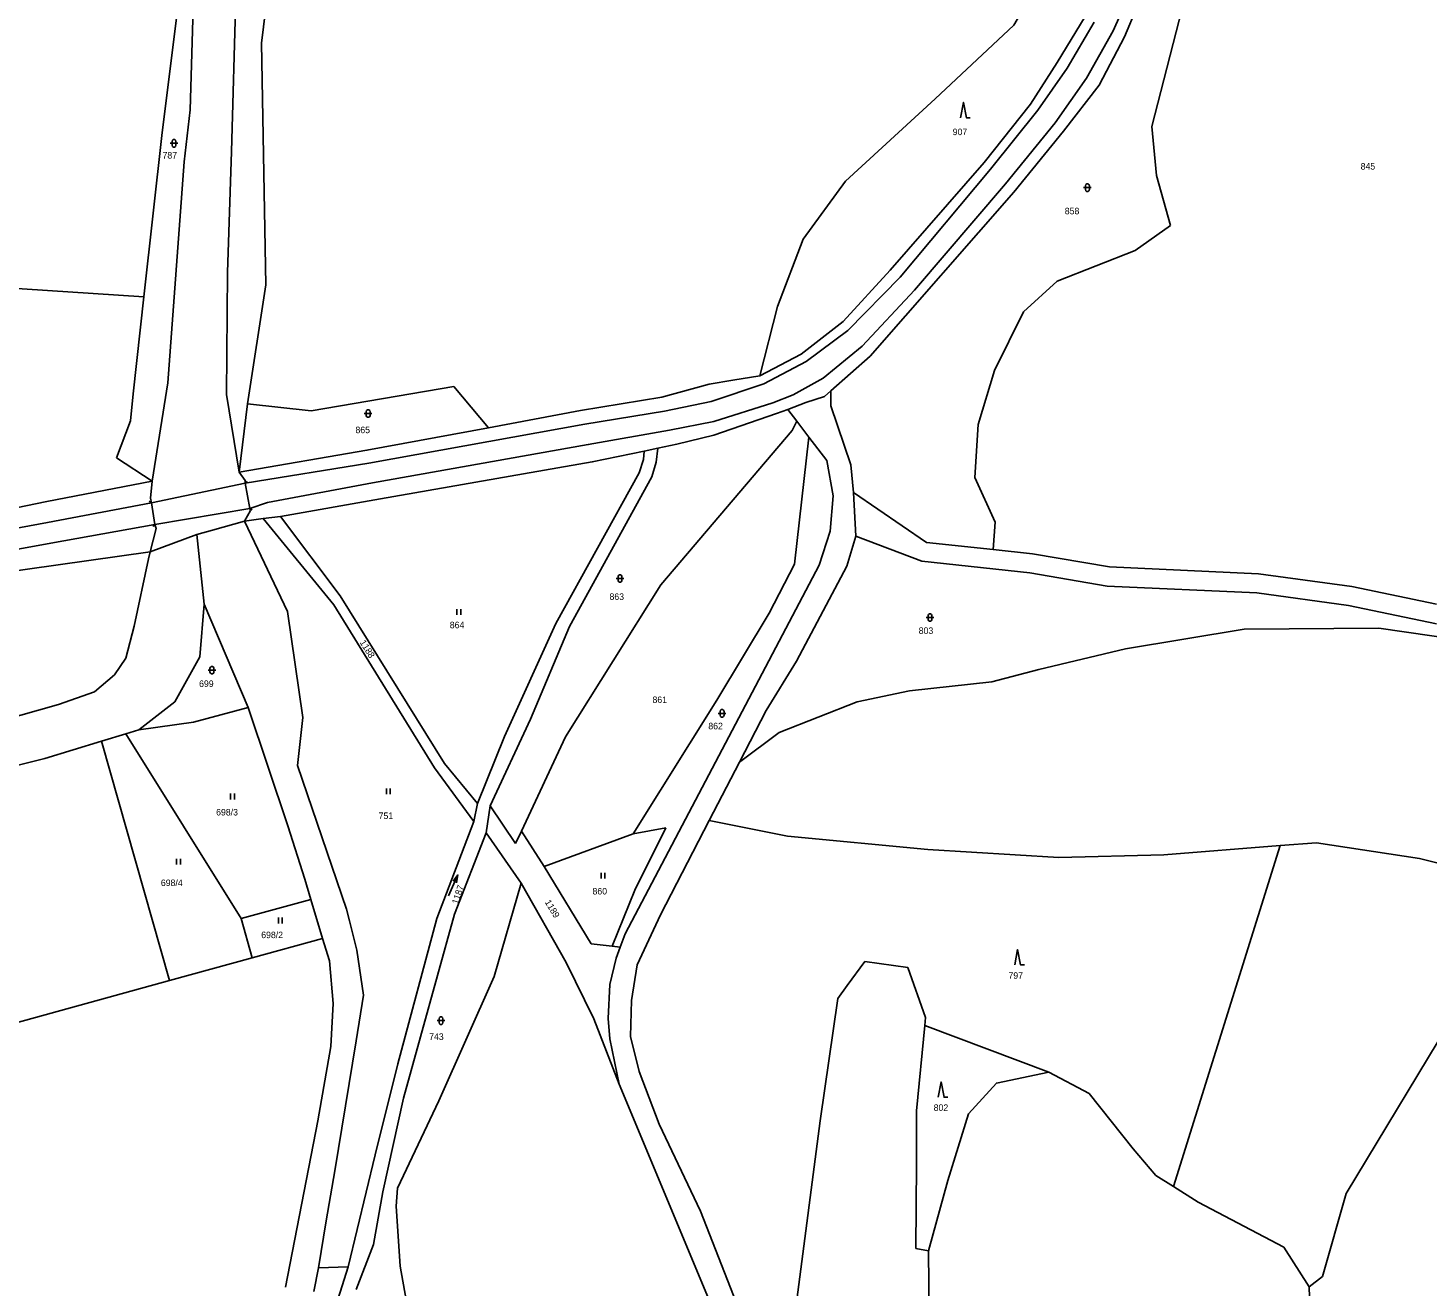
# Model space of a CAD drawing. Extents: x -812394 to -807601, y -1013097 to -1009266.
# Drawn here: x -809418.3 to -809053.2, y -1010907 to -1010578.9 of the extents above; entities that cross this region are included whole.
import ezdxf

# ---------------------------------------------------------------- set-up
doc = ezdxf.new("R2010")
doc.units = 0
for name, color, linetype in [('Default', 7, 'Continuous'), ('KN_HRANICE', 7, 'Continuous'), ('KN_KULTURY', 7, 'Continuous'), ('KN_PARCELY', 7, 'Continuous'), ('KN_SLUCKY', 7, 'Continuous')]:
    doc.layers.add(name, color=color, linetype=linetype)

# ---------------------------------------------------------------- blocks, each defined once
blk = doc.blocks.new('4201')
at = {"layer": 'Default'}
blk.add_line((0, 0), (-0.5, -0.5), dxfattribs=at)
blk = doc.blocks.new('306')
at = {"layer": 'Default'}
for p, q in [((-0.5, 1.5), (-0.5, 0)), ((0.5, 0), (0.5, 1.5))]:
    blk.add_line(p, q, dxfattribs=at)
blk = doc.blocks.new('308')
at = {"layer": 'Default'}
blk.add_lwpolyline([(-0.75, 0), (0, 4), (0.75, 0), (1.75, 0)], dxfattribs=at)
blk = doc.blocks.new('316')
at = {"layer": 'Default'}
for points in [[(-1, 1), (0.27, 1), (1, 1)], [(-0.5, 1.5), (-0.4, 1.79), (-0.15, 1.97), (0.16, 1.97), (0.41, 1.79), (0.51, 1.5), (0.51, 0.5), (0.41, 0.21), (0.16, 0.03), (-0.15, 0.03), (-0.4, 0.21), (-0.5, 0.5), (-0.5, 1.5)]]:
    blk.add_lwpolyline(points, dxfattribs=at)
blk = doc.blocks.new('802')
at = {"layer": 'Default'}
blk.add_line((-3, 0), (3, 0), dxfattribs=at)
blk.add_lwpolyline([(1, 0.5), (3, 0), (1, -0.5)], dxfattribs=at)

msp = doc.modelspace()

# ---------------------------------------------------------------- linework, layer by layer
at = {"layer": 'KN_HRANICE'}
for p, q in [((-809111.83, -1010552.24), (-809125.24, -1010604.55)), ((-809377.13, -1010557.12), (-809383.35, -1010606.11)), ((-809363.71, -1010556.15), (-809365.25, -1010611.02)), ((-809357.41, -1010582.83), (-809354.36, -1010558.01)), ((-809375.97, -1010600.22), (-809375.07, -1010568.14)), ((-809132.35, -1010581.13), (-809129.18, -1010573.51)), ((-809142.65, -1010575.85), (-809149.94, -1010587.88)), ((-809139.03, -1010593.73), (-809132.35, -1010581.13)), ((-809356.31, -1010645.84), (-809357.41, -1010582.83)), ((-809149.94, -1010587.88), (-809156.85, -1010598.68)), ((-809148.29, -1010605.74), (-809139.03, -1010593.73)), ((-809156.85, -1010598.68), (-809169, -1010613.92)), ((-809377.56, -1010613.76), (-809375.97, -1010600.22)), ((-809383.35, -1010606.11), (-809388.09, -1010648.93)), ((-809161.26, -1010621.62), (-809148.29, -1010605.74)), ((-809125.24, -1010604.55), (-809124.05, -1010617.34)), ((-809381.8, -1010671.36), (-809377.56, -1010613.76)), ((-809365.25, -1010611.02), (-809366.29, -1010642.62)), ((-809169, -1010613.92), (-809193.46, -1010642)), ((-809124.05, -1010617.34), (-809120.37, -1010630.38)), ((-809198.7, -1010664.41), (-809161.26, -1010621.62)), ((-809120.37, -1010630.38), (-809129.56, -1010636.86)), ((-809129.56, -1010636.86), (-809149.97, -1010644.82)), ((-809366.29, -1010642.62), (-809366.56, -1010674.35)), ((-809193.46, -1010642), (-809205.76, -1010655.37)), ((-809388.09, -1010648.93), (-809445.19, -1010645.2)), ((-809361.06, -1010676.78), (-809356.31, -1010645.84)), ((-809149.97, -1010644.82), (-809158.75, -1010652.82)), ((-809390.89, -1010674.22), (-809388.09, -1010648.93)), ((-809158.75, -1010652.82), (-809166.27, -1010668.11)), ((-809205.76, -1010655.37), (-809216.72, -1010663.86)), ((-809216.72, -1010663.86), (-809227.49, -1010669.52)), ((-809208.98, -1010673.47), (-809198.7, -1010664.41)), ((-809166.27, -1010668.11), (-809170.54, -1010682.2)), ((-809385.89, -1010696.99), (-809381.8, -1010671.36)), ((-809307.29, -1010672.33), (-809344.46, -1010678.63)), ((-809298.22, -1010683.04), (-809307.29, -1010672.33)), ((-809240.7, -1010671.73), (-809253.03, -1010675.1)), ((-809234.5, -1010670.64), (-809240.7, -1010671.73)), ((-809227.49, -1010669.52), (-809234.5, -1010670.64)), ((-809391.53, -1010681.27), (-809390.89, -1010674.22)), ((-809366.56, -1010674.35), (-809363.24, -1010694.6)), ((-809253.03, -1010675.1), (-809274.21, -1010678.59)), ((-809210.6, -1010674.9), (-809215.44, -1010676.51)), ((-809210.6, -1010674.9), (-809208.98, -1010673.47)), ((-809208.98, -1010677.34), (-809208.98, -1010673.47)), ((-809363.24, -1010694.6), (-809361.06, -1010676.78)), ((-809344.46, -1010678.63), (-809361.06, -1010676.78)), ((-809274.21, -1010678.59), (-809298.22, -1010683.04)), ((-809239.47, -1010685.01), (-809223.12, -1010679.37)), ((-809223.12, -1010679.37), (-809220.13, -1010678.26)), ((-809220.13, -1010678.26), (-809215.44, -1010676.51)), ((-809220.13, -1010678.26), (-809217.82, -1010681.31)), ((-809203.72, -1010692.71), (-809208.98, -1010677.34)), ((-809395.22, -1010690.85), (-809391.53, -1010681.27)), ((-809217.82, -1010681.31), (-809219.05, -1010683.79)), ((-809217.82, -1010681.31), (-809214.65, -1010685.5)), ((-809170.54, -1010682.2), (-809171.37, -1010695.98)), ((-809219.05, -1010683.79), (-809253.31, -1010723.95)), ((-809249.11, -1010687.36), (-809239.47, -1010685.01)), ((-809218.43, -1010718.59), (-809214.65, -1010685.5)), ((-809214.65, -1010685.5), (-809210.02, -1010691.61)), ((-809254.05, -1010688.39), (-809257.64, -1010689.14)), ((-809254.05, -1010688.39), (-809254.52, -1010692.03)), ((-809249.11, -1010687.36), (-809254.05, -1010688.39)), ((-809385.89, -1010696.99), (-809395.22, -1010690.85)), ((-809254.52, -1010692.03), (-809255.59, -1010695.88)), ((-809210.02, -1010691.61), (-809208.36, -1010700.77)), ((-809203.06, -1010699.92), (-809203.72, -1010692.71)), ((-809413.39, -1010702.26), (-809385.89, -1010696.99)), ((-809360.44, -1010704.12), (-809361.63, -1010697.51)), ((-809255.59, -1010695.88), (-809277.13, -1010734.81)), ((-809171.37, -1010695.98), (-809166.1, -1010707.64)), ((-809208.36, -1010700.77), (-809209.11, -1010710.03)), ((-809183.97, -1010712.92), (-809203.06, -1010699.92)), ((-809203.06, -1010699.92), (-809202.45, -1010711.33)), ((-809413.39, -1010702.26), (-809437.86, -1010707.26)), ((-809385.19, -1010708.29), (-809386.06, -1010702.58)), ((-809370.19, -1010709.75), (-809361.8, -1010707.43)), ((-809356.99, -1010706.69), (-809361.8, -1010707.43)), ((-809361.8, -1010707.43), (-809350.65, -1010730.95)), ((-809352.49, -1010706.15), (-809356.99, -1010706.69)), ((-809356.99, -1010706.69), (-809338.51, -1010729.21)), ((-809336.86, -1010726.87), (-809352.49, -1010706.15)), ((-809166.1, -1010707.64), (-809166.67, -1010714.78)), ((-809374.26, -1010710.88), (-809386.46, -1010715.35)), ((-809370.19, -1010709.75), (-809374.26, -1010710.88)), ((-809372.39, -1010729.01), (-809374.26, -1010710.88)), ((-809209.11, -1010710.03), (-809212.01, -1010718.89)), ((-809204.77, -1010719.08), (-809202.45, -1010711.33)), ((-809202.45, -1010711.33), (-809185.19, -1010717.8)), ((-809434.83, -1010722.26), (-809386.46, -1010715.35)), ((-809386.46, -1010715.35), (-809386.86, -1010717.18)), ((-809166.67, -1010714.78), (-809183.97, -1010712.92)), ((-809156.41, -1010715.89), (-809166.67, -1010714.78)), ((-809136.31, -1010719.31), (-809156.41, -1010715.89)), ((-809212.01, -1010718.89), (-809262.62, -1010814.93)), ((-809225, -1010731.39), (-809218.43, -1010718.59)), ((-809217.89, -1010743.91), (-809204.77, -1010719.08)), ((-809185.19, -1010717.8), (-809157.07, -1010720.85)), ((-809097.41, -1010721.08), (-809136.31, -1010719.31)), ((-809157.07, -1010720.85), (-809136.87, -1010724.29)), ((-809073.09, -1010724.43), (-809097.41, -1010721.08)), ((-809309.65, -1010770.56), (-809336.86, -1010726.87)), ((-809253.31, -1010723.95), (-809278.14, -1010763.62)), ((-809136.87, -1010724.29), (-809097.85, -1010726.06)), ((-809097.85, -1010726.06), (-809073.97, -1010729.35)), ((-809051.04, -1010729.02), (-809073.09, -1010724.43)), ((-809372.39, -1010729.01), (-809360.9, -1010755.91)), ((-809350.65, -1010730.95), (-809346.62, -1010758.53)), ((-809338.51, -1010729.21), (-809312.31, -1010771.66)), ((-809073.97, -1010729.35), (-809051.02, -1010734.13)), ((-809294.04, -1010763.48), (-809280.64, -1010734.02)), ((-809238.67, -1010754.07), (-809225, -1010731.39)), ((-809277.13, -1010734.81), (-809287.3, -1010759.01)), ((-809132.16, -1010740.65), (-809101.15, -1010735.55)), ((-809101.15, -1010735.55), (-809066.09, -1010735.31)), ((-809066.09, -1010735.31), (-809035.42, -1010739.75)), ((-809154.74, -1010746.08), (-809132.16, -1010740.65)), ((-809225.81, -1010756.71), (-809217.89, -1010743.91)), ((-809166.94, -1010749.26), (-809154.74, -1010746.08)), ((-809202.08, -1010754.49), (-809188.43, -1010751.6)), ((-809188.43, -1010751.6), (-809166.94, -1010749.26)), ((-809350.5, -1010786.79), (-809360.9, -1010755.91)), ((-809260.51, -1010788.84), (-809238.67, -1010754.07)), ((-809222.4, -1010762.48), (-809202.08, -1010754.49)), ((-809346.62, -1010758.53), (-809348.01, -1010771.1)), ((-809287.3, -1010759.01), (-809297.76, -1010781.54)), ((-809232.78, -1010770.16), (-809225.81, -1010756.71)), ((-809399.13, -1010764.75), (-809392.8, -1010762.82)), ((-809392.8, -1010762.82), (-809389.38, -1010761.78)), ((-809392.8, -1010762.82), (-809362.69, -1010810.95)), ((-809301.09, -1010780.94), (-809294.04, -1010763.48)), ((-809278.14, -1010763.62), (-809289.64, -1010788.2)), ((-809232.78, -1010770.16), (-809222.4, -1010762.48)), ((-809413.92, -1010769.26), (-809399.13, -1010764.75)), ((-809399.13, -1010764.75), (-809381.38, -1010827.1)), ((-809450.75, -1010778.5), (-809413.92, -1010769.26)), ((-809301.09, -1010780.94), (-809309.65, -1010770.56)), ((-809240.68, -1010785.42), (-809232.78, -1010770.16)), ((-809312.31, -1010771.66), (-809302.07, -1010785.66)), ((-809302.07, -1010785.66), (-809301.09, -1010780.94)), ((-809297.76, -1010781.54), (-809298.85, -1010788.58)), ((-809291.14, -1010791.4), (-809297.76, -1010781.54)), ((-809311.7, -1010810.97), (-809302.07, -1010785.66)), ((-809253.38, -1010809.96), (-809240.68, -1010785.42)), ((-809220.26, -1010789.46), (-809240.68, -1010785.42)), ((-809346.14, -1010800.65), (-809350.5, -1010786.79)), ((-809298.85, -1010788.58), (-809307.08, -1010809.79)), ((-809298.85, -1010788.58), (-809289.73, -1010801.7)), ((-809289.64, -1010788.2), (-809291.14, -1010791.4)), ((-809283.71, -1010797.35), (-809289.64, -1010788.2)), ((-809283.71, -1010797.35), (-809260.51, -1010788.84)), ((-809260.51, -1010788.84), (-809252.02, -1010787.31)), ((-809260.08, -1010803.57), (-809252.02, -1010787.31)), ((-809183.63, -1010792.94), (-809220.26, -1010789.46)), ((-809149.52, -1010795.02), (-809183.63, -1010792.94)), ((-809091.8, -1010791.95), (-809122.15, -1010794.33)), ((-809119.63, -1010880.82), (-809091.8, -1010791.95)), ((-809082.28, -1010791.2), (-809091.8, -1010791.95)), ((-809055.45, -1010795.34), (-809082.28, -1010791.2)), ((-809122.15, -1010794.33), (-809149.52, -1010795.02)), ((-809029.02, -1010801.9), (-809055.45, -1010795.34)), ((-809271.44, -1010817.56), (-809283.71, -1010797.35)), ((-809344.54, -1010805.97), (-809346.14, -1010800.65)), ((-809289.73, -1010801.7), (-809296.75, -1010826.06)), ((-809289.73, -1010801.7), (-809277.95, -1010822.39)), ((-809265.96, -1010818.15), (-809260.08, -1010803.57)), ((-809362.69, -1010810.95), (-809344.54, -1010805.97)), ((-809341.48, -1010816.14), (-809344.54, -1010805.97)), ((-809359.87, -1010821.19), (-809362.69, -1010810.95)), ((-809321.83, -1010848.82), (-809311.7, -1010810.97)), ((-809307.08, -1010809.79), (-809320.4, -1010857.76)), ((-809259.44, -1010823.03), (-809253.38, -1010809.96)), ((-809262.62, -1010814.93), (-809263.88, -1010818.37)), ((-809341.48, -1010816.14), (-809359.87, -1010821.19)), ((-809339.72, -1010821.99), (-809341.48, -1010816.14)), ((-809265.96, -1010818.15), (-809271.44, -1010817.56)), ((-809263.88, -1010818.37), (-809265.96, -1010818.15)), ((-809264.94, -1010821.27), (-809263.88, -1010818.37)), ((-809359.87, -1010821.19), (-809381.38, -1010827.1)), ((-809338.73, -1010833.11), (-809339.72, -1010821.99)), ((-809266.62, -1010828.14), (-809264.94, -1010821.27)), ((-809277.95, -1010822.39), (-809270.78, -1010837.06)), ((-809260.97, -1010832.29), (-809259.44, -1010823.03)), ((-809381.38, -1010827.1), (-809492.16, -1010857.54)), ((-809296.75, -1010826.06), (-809311.13, -1010858.5)), ((-809267.01, -1010837.04), (-809266.62, -1010828.14)), ((-809204.66, -1010828.39), (-809207.16, -1010831.81)), ((-809339.33, -1010844.32), (-809338.73, -1010833.11)), ((-809261.18, -1010841.69), (-809260.97, -1010832.29)), ((-809207.16, -1010831.81), (-809211.78, -1010863.69)), ((-809045.32, -1010834.15), (-809074.57, -1010882.59)), ((-809270.78, -1010837.06), (-809264.15, -1010854.13)), ((-809266.59, -1010842.31), (-809267.01, -1010837.04)), ((-809152.12, -1010851.01), (-809184.46, -1010838.79)), ((-809264.15, -1010854.13), (-809266.59, -1010842.31)), ((-809258.97, -1010850.83), (-809261.18, -1010841.69)), ((-809342.76, -1010863.71), (-809339.33, -1010844.32)), ((-809327.78, -1010872.52), (-809321.83, -1010848.82)), ((-809253.7, -1010864.58), (-809258.97, -1010850.83)), ((-809152.12, -1010851.01), (-809141.63, -1010856.55)), ((-809264.15, -1010854.13), (-809237.69, -1010917.44)), ((-809320.4, -1010857.76), (-809325.74, -1010882.17)), ((-809311.13, -1010858.5), (-809321.92, -1010881.25)), ((-809141.63, -1010856.55), (-809130.13, -1010870.93)), ((-809351.15, -1010907.01), (-809342.76, -1010863.71)), ((-809242.93, -1010887.17), (-809253.7, -1010864.58)), ((-809211.78, -1010863.69), (-809217.85, -1010910.29)), ((-809334.79, -1010901.69), (-809327.78, -1010872.52)), ((-809130.13, -1010870.93), (-809124.17, -1010877.95)), ((-809124.17, -1010877.95), (-809119.63, -1010880.82)), ((-809325.74, -1010882.17), (-809328.19, -1010895.88)), ((-809321.92, -1010881.25), (-809322.29, -1010885.89)), ((-809119.63, -1010880.82), (-809113.21, -1010884.87)), ((-809074.57, -1010882.59), (-809080.73, -1010904.26)), ((-809322.29, -1010885.89), (-809321.27, -1010901.54)), ((-809228.17, -1010924.96), (-809242.93, -1010887.17)), ((-809113.21, -1010884.87), (-809090.86, -1010896.55)), ((-809340.51, -1010889.72), (-809342.56, -1010901.99)), ((-809328.19, -1010895.88), (-809332.71, -1010907.64)), ((-809183.47, -1010897.59), (-809186.8, -1010896.95)), ((-809182.59, -1010976.12), (-809183.47, -1010897.59)), ((-809090.86, -1010896.55), (-809084.22, -1010906.93)), ((-809342.56, -1010901.99), (-809343.75, -1010908.11)), ((-809342.56, -1010901.99), (-809334.79, -1010901.69)), ((-809339.74, -1010917.13), (-809334.79, -1010901.69)), ((-809321.27, -1010901.54), (-809315.42, -1010933.7)), ((-809080.73, -1010904.26), (-809084.22, -1010906.93)), ((-809084.22, -1010906.93), (-809083.93, -1010915.3))]:
    msp.add_line(p, q, dxfattribs=at)
for points in [[(-809227.49, -1010669.52), (-809222.89, -1010651.43), (-809216.16, -1010633.87), (-809205.12, -1010618.75), (-809181.78, -1010597.36), (-809161.27, -1010578.12), (-809154.48, -1010566.46), (-809151.95, -1010550.2), (-809148.31, -1010534.06), (-809144.6, -1010520.48), (-809143.21, -1010500.19), (-809145.36, -1010479.96)], [(-809363.24, -1010694.6), (-809329.9, -1010688.92), (-809298.22, -1010683.04)], [(-809257.64, -1010689.14), (-809271.18, -1010691.97), (-809326.4, -1010701.59), (-809352.49, -1010706.15)], [(-809257.64, -1010689.14), (-809257.8, -1010691.32), (-809258.9, -1010694.81), (-809280.64, -1010734.02)], [(-809386.06, -1010702.58), (-809386.34, -1010701.43), (-809385.89, -1010696.99)], [(-809361.63, -1010697.51), (-809361.69, -1010696.82), (-809363.24, -1010694.6)], [(-809361.8, -1010707.43), (-809360.26, -1010704.65), (-809360.44, -1010704.12)], [(-809386.46, -1010715.35), (-809384.87, -1010709.29), (-809385.19, -1010708.29)], [(-809386.86, -1010717.18), (-809390.64, -1010734.74), (-809392.82, -1010743.13), (-809395.75, -1010747.43), (-809400.98, -1010751.89), (-809410.38, -1010755.21), (-809425.36, -1010759.45), (-809455.87, -1010766.45), (-809482.83, -1010772.6), (-809507.48, -1010779.27)], [(-809389.38, -1010761.78), (-809380.01, -1010754.48), (-809373.51, -1010742.73), (-809372.39, -1010729.01)], [(-809360.9, -1010755.91), (-809375.18, -1010759.76), (-809389.38, -1010761.78)], [(-809334.49, -1010811.54), (-809335.27, -1010808.48), (-809348.01, -1010771.1)], [(-809340.51, -1010889.72), (-809338.33, -1010876.69), (-809332.75, -1010842.86), (-809330.81, -1010830.91), (-809332.56, -1010819.17), (-809334.49, -1010811.54)], [(-809204.66, -1010828.39), (-809200.08, -1010822.13), (-809188.88, -1010823.74), (-809184.26, -1010836.72), (-809184.46, -1010838.79)], [(-809186.8, -1010896.95), (-809186.63, -1010874.99), (-809186.59, -1010861.1), (-809184.46, -1010838.79)], [(-809152.12, -1010851.01), (-809165.76, -1010853.83), (-809173.03, -1010861.88), (-809178.44, -1010879.24), (-809183.47, -1010897.59)]]:
    msp.add_lwpolyline(points, dxfattribs=at)
at = {"layer": 'KN_SLUCKY'}
for p, q in [((-809386.06, -1010702.58), (-809361.63, -1010697.51)), ((-809360.44, -1010704.12), (-809385.19, -1010708.29))]:
    msp.add_line(p, q, dxfattribs=at)
for points in [[(-809360.44, -1010704.12), (-809355.84, -1010702.51), (-809328.45, -1010697.39), (-809272.21, -1010687.44), (-809251.05, -1010683.67), (-809239.49, -1010681.41), (-809224.04, -1010676.54), (-809218.8, -1010674.51), (-809210.97, -1010670.13), (-809200.79, -1010661.8), (-809187.11, -1010647.21), (-809163.44, -1010619.45), (-809150.48, -1010603.59), (-809142.31, -1010591.91), (-809135.38, -1010579.58), (-809131.33, -1010570.55)], [(-809140.31, -1010577.36), (-809147.31, -1010589.34), (-809154.97, -1010600.3), (-809167.32, -1010615.7), (-809190.91, -1010643.78), (-809204.52, -1010657.67), (-809215.35, -1010665.74), (-809226.43, -1010671.57), (-809240.16, -1010676.22), (-809252.29, -1010678.72), (-809273.06, -1010682.12), (-809329.44, -1010692.29), (-809361.63, -1010697.51)], [(-809462.54, -1010716.59), (-809456.78, -1010715.47), (-809450.24, -1010714.77), (-809436.78, -1010712.1), (-809413.21, -1010707.7), (-809386.06, -1010702.58)], [(-809385.19, -1010708.29), (-809412.36, -1010713.13), (-809435.74, -1010717.37), (-809462.86, -1010722.22)]]:
    msp.add_lwpolyline(points, dxfattribs=at)

# ---------------------------------------------------------------- block references
at = {"layer": 'KN_KULTURY'}
for name, p in [('308', (-809174.37, -1010602.27)), ('316', (-809380.22, -1010609.92)), ('316', (-809142.05, -1010621.48)), ('316', (-809329.6, -1010680.36)), ('316', (-809263.95, -1010723.33)), ('306', (-809305.94, -1010731.8)), ('316', (-809183.11, -1010733.51)), ('316', (-809370.35, -1010747.22)), ('316', (-809237.32, -1010758.48)), ('306', (-809364.96, -1010779.89)), ('306', (-809324.32, -1010778.54)), ('306', (-809379.04, -1010796.91)), ('306', (-809268.37, -1010800.54)), ('306', (-809352.48, -1010812.22)), ('308', (-809160.24, -1010823.02)), ('316', (-809310.6, -1010838.56)), ('308', (-809180.19, -1010857.51))]:
    msp.add_blockref(name, p, dxfattribs=at)
at = {"layer": 'KN_KULTURY', "rotation": 66.062034}
msp.add_blockref('802', (-809307.4, -1010802.33), dxfattribs=at)
at = {"layer": 'KN_SLUCKY'}
for p, rotation in [((-809361.63, -1010697.51), -174.70544900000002), ((-809386.06, -1010702.58), -76.90155299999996), ((-809360.44, -1010704.12), 104.507502)]:
    msp.add_blockref('4201', p, dxfattribs=dict(at, rotation=rotation))
msp.add_blockref('4201', (-809385.19, -1010708.29), dxfattribs=at)

# ---------------------------------------------------------------- texts
at = {"layer": 'KN_PARCELY'}
for s, p in [('907', (-809177.18, -1010606.79)), ('787', (-809383.22, -1010612.9)), ('845', (-809070.81, -1010615.77)), ('858', (-809147.95, -1010627.42)), ('865', (-809332.91, -1010684.46)), ('863', (-809266.67, -1010727.92)), ('864', (-809308.31, -1010735.3)), ('803', (-809186.04, -1010736.78)), ('699', (-809373.68, -1010750.6)), ('861', (-809255.46, -1010754.79)), ('862', (-809240.9, -1010761.63)), ('698/3', (-809369.24, -1010784.09)), ('751', (-809326.87, -1010785.01)), ('698/4', (-809383.65, -1010802.49)), ('860', (-809271.1, -1010804.68)), ('698/2', (-809357.48, -1010816.06)), ('797', (-809162.64, -1010826.64)), ('743', (-809313.7, -1010842.58)), ('802', (-809182.14, -1010861.09))]:
    msp.add_text(s, height=1.7, dxfattribs=at).set_placement(p)
for s, rotation, p in [('1188', 302.006, (-809331.87, -1010738.99)), ('1187', 71.161, (-809306.22, -1010807.37)), ('1189', 300.975, (-809283.61, -1010806.67))]:
    msp.add_text(s, height=1.7, rotation=rotation, dxfattribs=at).set_placement(p)

doc.saveas('drawing.dxf')
